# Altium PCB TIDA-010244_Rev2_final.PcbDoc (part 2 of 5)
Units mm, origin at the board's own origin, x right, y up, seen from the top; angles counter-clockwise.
Board outline 155.23 x 187.6 mm, 4 copper layers (GND/Signal 1, Solid GND Layer 1, Solid Power Layer 1, GND/Signal Layer 2), stack 1.59 mm thick; 350 components, 237 nets, 1153 pads, 380 vias.
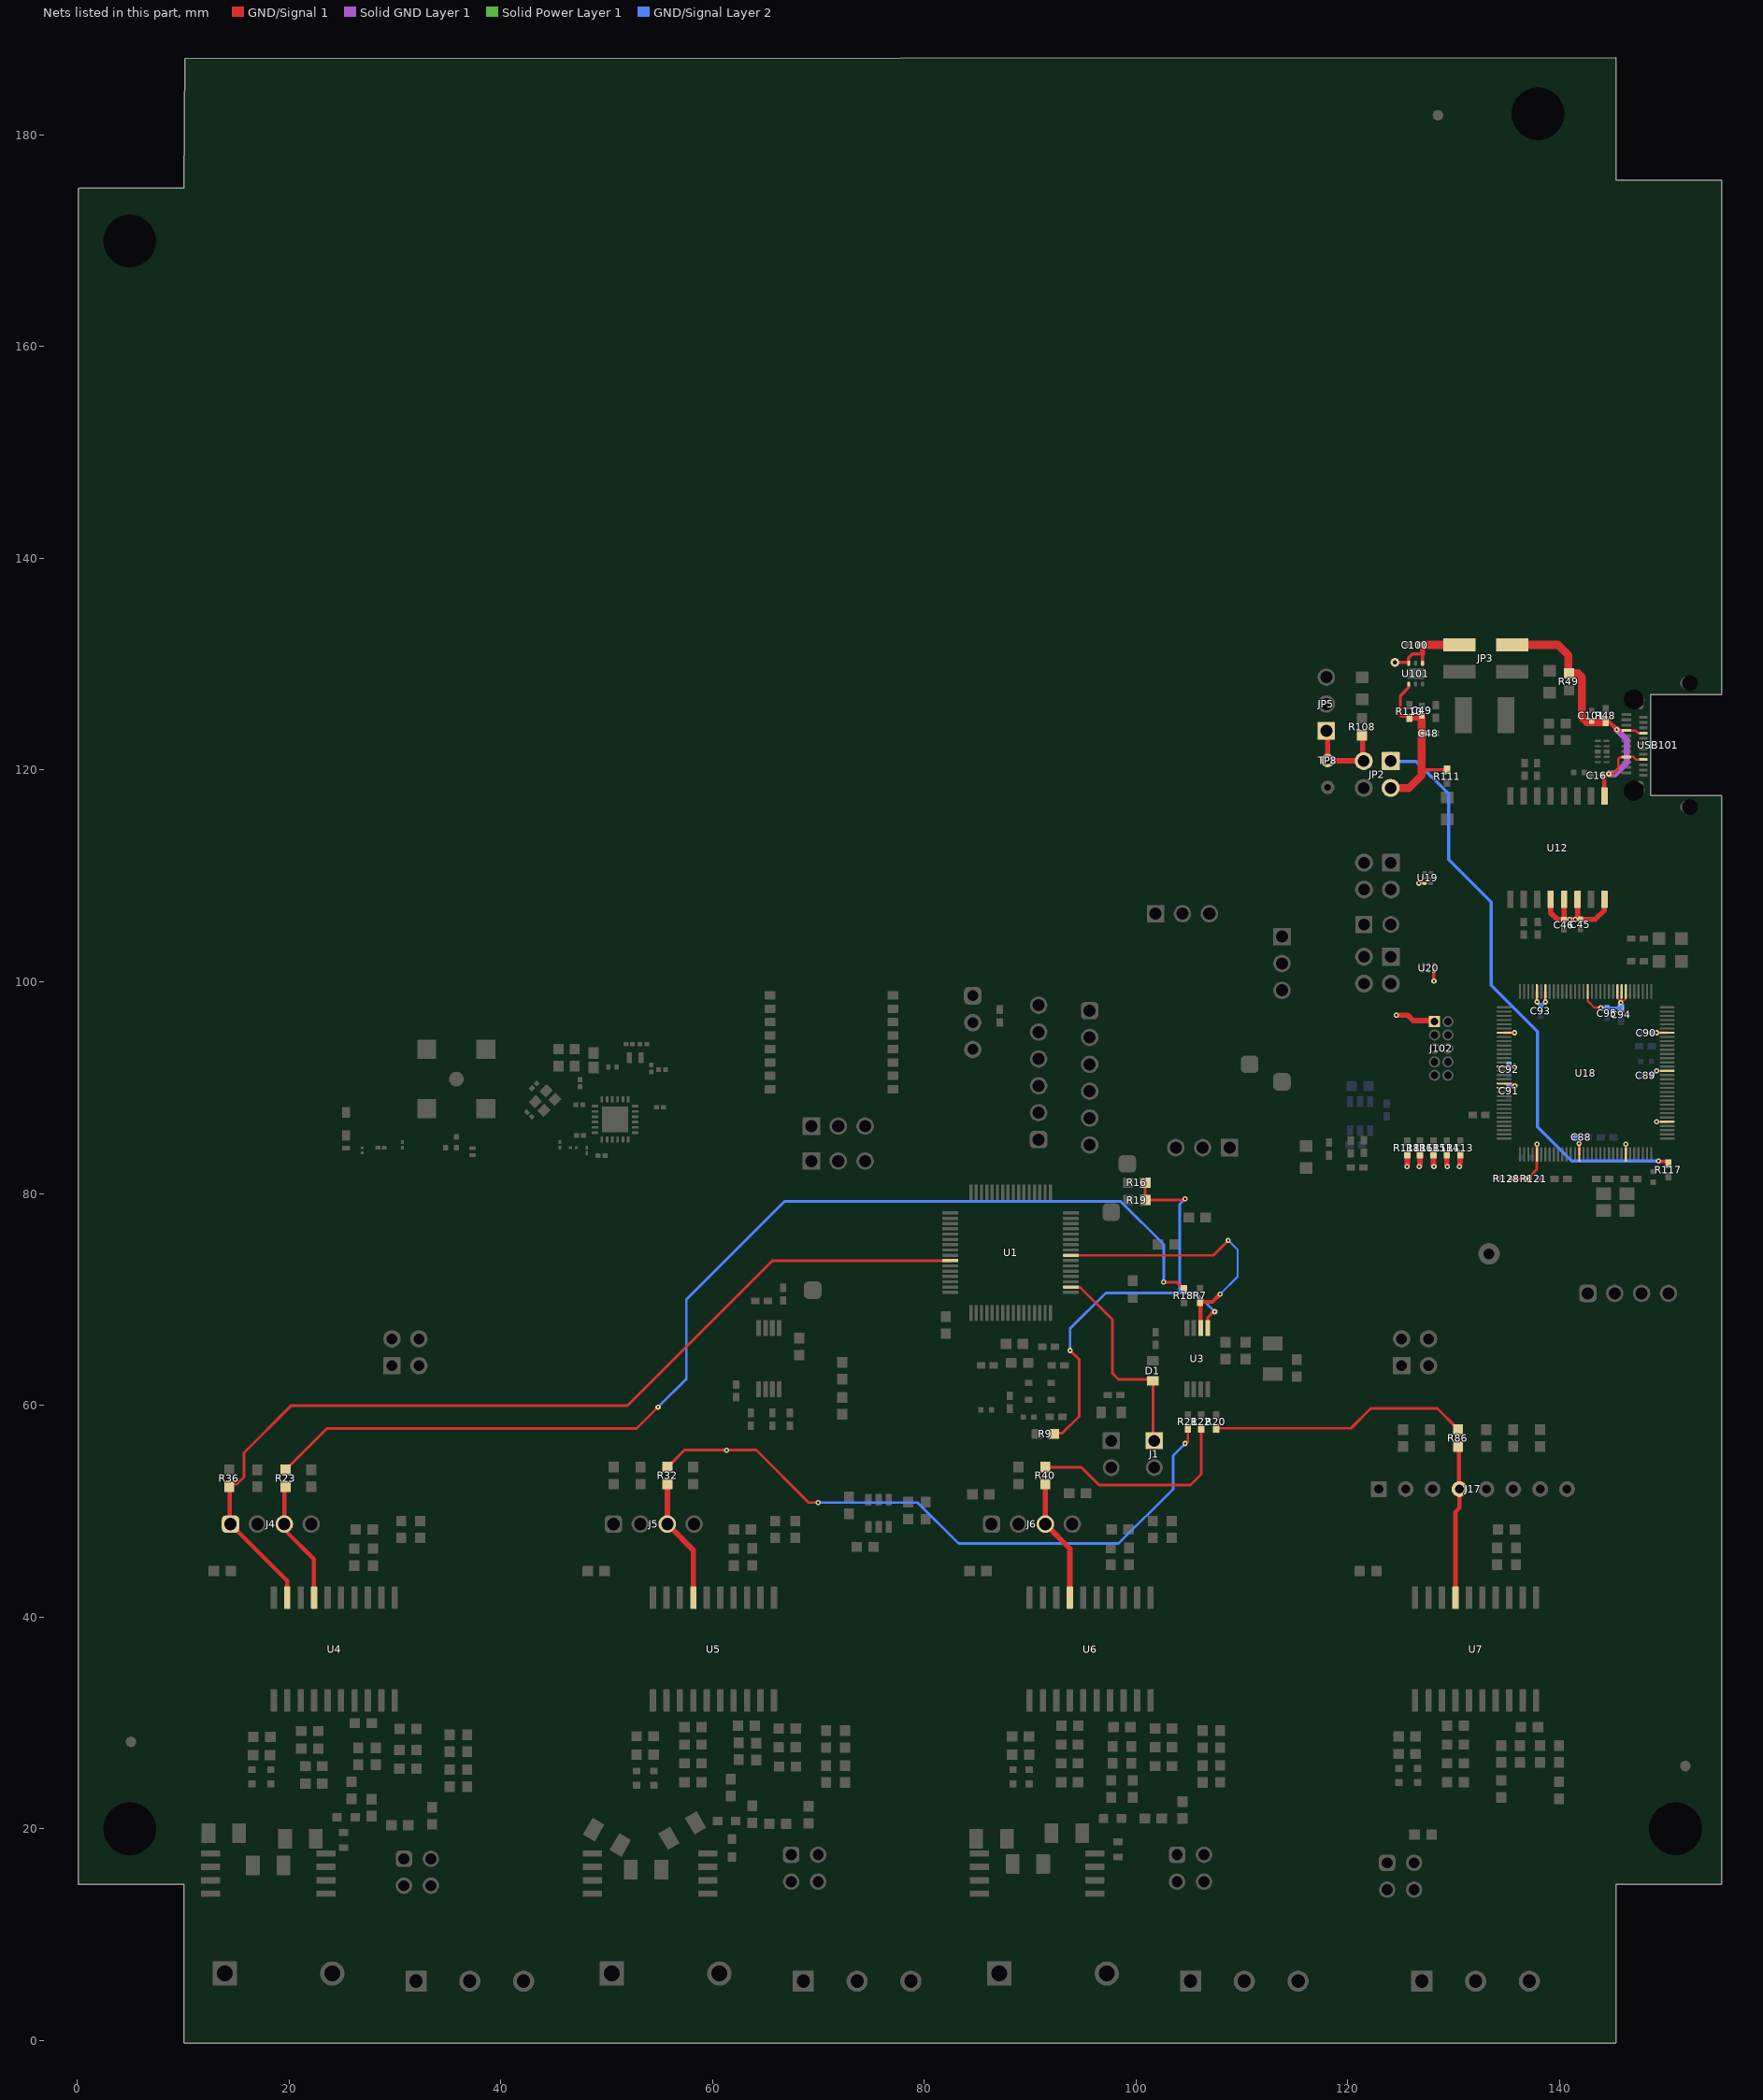
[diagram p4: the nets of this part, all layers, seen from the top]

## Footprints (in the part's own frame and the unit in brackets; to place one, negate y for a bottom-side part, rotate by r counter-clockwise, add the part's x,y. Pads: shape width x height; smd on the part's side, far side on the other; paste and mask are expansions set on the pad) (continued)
FP-MUP-U22001_CONN_USB_8MM94_8MM0-MFG [mm]
  rrect100% 0.6x1.9 hole 1.9 slot 0.6 at 0 deg: 1(-4.32,3.35) 2(4.32,3.35)
  round 1.207 smd: 1(-4.25,2.92) 2(4.25,2.92)
  round 1.207 smd far side: 1(-4.25,2.92) 2(4.25,2.92)
  rrect100% 1.25x0.7 hole 0.7 slot 1.25 at 0 deg: 1(-3.995,2.75) 2(3.995,2.75)
  rrect100% 0.7x1.5 hole 1.5 slot 0.7 at 0 deg: 3(-5.85,-1.95) 4(5.85,-1.95)
  round 1.17 smd far side: 3(-5.85,-1.625) 4(5.85,-1.625)
  round 1.17 smd: 3(-5.85,-1.625) 4(5.85,-1.625)
  rrect37% 0.27x0.9 smd: A1(-2.625,4.05) A2(-2.125,4.05) A3(-1.625,4.05) A4(-1.125,4.05) A5(-0.625,4.05) A6(-0.125,4.05) A7(0.375,4.05) A8(0.875,4.05) A9(1.375,4.05) A10(1.875,4.05) A11(2.375,4.05) A12(2.875,4.05)
  rrect37% 0.27x0.8 smd: B1(2.625,2.45) B2(2.125,2.45) B3(1.625,2.45) B4(1.125,2.45) B5(0.625,2.45) B6(0.125,2.45) B7(-0.375,2.45) B8(-0.875,2.45) B9(-1.375,2.45) B10(-1.875,2.45) B11(-2.375,2.45) B12(-2.875,2.45)
  GND/Signal 1 region: -6.5,-2.349 -6.5,-2.472 -6.411,-2.701 -6.244,-2.882 -6.023,-2.99 -5.9,-2.999 -5.9,-2.999 -5.833,-3.004 -5.699,-2.987 -5.572,-2.942 -5.457,-2.873 -5.358,-2.781 -5.281,-2.672 -5.227,-2.548 -5.2,-2.416 -5.2,-2.349 -5.2,-2.349 -5.2,-0.749 -5.2,-0.65 -5.276,-0.466 -5.417,-0.325 -5.601,-0.249 -5.7,-0.249 -5.7,-0.249 -6,-0.249 -6.099,-0.249 -6.283,-0.325 -6.424,-0.466 -6.5,-0.65 -6.5,-0.749 -6.5,-0.749
  GND/Signal 1 region: 6.5,-2.349 6.5,-2.472 6.411,-2.701 6.244,-2.882 6.023,-2.99 5.9,-2.999 5.833,-3.004 5.699,-2.987 5.572,-2.942 5.457,-2.873 5.358,-2.781 5.281,-2.672 5.227,-2.548 5.2,-2.416 5.2,-2.349 5.2,-2.349 5.2,-0.749 5.2,-0.65 5.276,-0.466 5.417,-0.325 5.601,-0.249 5.7,-0.249 5.7,-0.249 6,-0.249 6.099,-0.249 6.283,-0.325 6.424,-0.466 6.5,-0.65 6.5,-0.749 6.5,-0.749
  GND/Signal 1 region: -3.72,3.35 -3.72,4.05 -3.72,4.169 -3.811,4.39 -3.98,4.559 -4.201,4.65 -4.32,4.65 -4.439,4.65 -4.66,4.559 -4.829,4.39 -4.92,4.169 -4.92,4.05 -4.92,4.05 -4.92,2.85 -4.92,2.731 -4.829,2.51 -4.66,2.341 -4.439,2.25 -4.32,2.25 -4.32,2.25 -3.82,2.25 -3.711,2.25 -3.508,2.334 -3.354,2.488 -3.27,2.691 -3.27,2.8 -3.268,2.898 -3.332,3.082 -3.456,3.233 -3.624,3.332 -3.72,3.35
  GND/Signal 1 region: 3.72,3.35 3.72,4.05 3.72,4.169 3.811,4.39 3.98,4.559 4.201,4.65 4.32,4.65 4.439,4.65 4.66,4.559 4.829,4.39 4.92,4.169 4.92,4.05 4.92,4.05 4.92,2.85 4.92,2.731 4.829,2.51 4.66,2.341 4.439,2.25 4.32,2.25 4.32,2.25 3.82,2.25 3.711,2.25 3.508,2.334 3.354,2.488 3.27,2.691 3.27,2.8 3.268,2.898 3.332,3.082 3.456,3.233 3.624,3.332 3.72,3.35 3.72,3.35
  GND/Signal Layer 2 region: -6.5,-2.349 -6.5,-2.472 -6.411,-2.701 -6.244,-2.882 -6.023,-2.99 -5.9,-2.999 -5.833,-3.004 -5.699,-2.987 -5.572,-2.942 -5.457,-2.873 -5.358,-2.781 -5.281,-2.672 -5.227,-2.548 -5.2,-2.416 -5.2,-2.349 -5.2,-2.349 -5.2,-0.749 -5.2,-0.65 -5.276,-0.466 -5.417,-0.325 -5.601,-0.249 -5.7,-0.249 -5.7,-0.249 -6,-0.249 -6.099,-0.249 -6.283,-0.325 -6.424,-0.466 -6.5,-0.65 -6.5,-0.749 -6.5,-0.749
  GND/Signal Layer 2 region: 6.5,-2.349 6.5,-2.472 6.411,-2.701 6.244,-2.882 6.023,-2.99 5.9,-2.999 5.833,-3.004 5.699,-2.987 5.572,-2.942 5.457,-2.873 5.358,-2.781 5.281,-2.672 5.227,-2.548 5.2,-2.416 5.2,-2.349 5.2,-2.349 5.2,-0.749 5.2,-0.65 5.276,-0.466 5.417,-0.325 5.601,-0.249 5.7,-0.249 5.7,-0.249 6,-0.249 6.099,-0.249 6.283,-0.325 6.424,-0.466 6.5,-0.65 6.5,-0.749 6.5,-0.749
  GND/Signal Layer 2 region: -3.72,3.35 -3.72,4.05 -3.72,4.169 -3.811,4.39 -3.98,4.559 -4.201,4.65 -4.32,4.65 -4.439,4.65 -4.66,4.559 -4.829,4.39 -4.92,4.169 -4.92,4.05 -4.92,4.05 -4.92,2.85 -4.92,2.731 -4.829,2.51 -4.66,2.341 -4.439,2.25 -4.32,2.25 -4.32,2.25 -3.82,2.25 -3.711,2.25 -3.508,2.334 -3.354,2.488 -3.27,2.691 -3.27,2.8 -3.268,2.898 -3.332,3.082 -3.456,3.233 -3.624,3.332 -3.72,3.35
  GND/Signal Layer 2 region: 3.72,3.35 3.72,4.05 3.72,4.169 3.811,4.39 3.98,4.559 4.201,4.65 4.32,4.65 4.439,4.65 4.66,4.559 4.829,4.39 4.92,4.169 4.92,4.05 4.92,4.05 4.92,2.85 4.92,2.731 4.829,2.51 4.66,2.341 4.439,2.25 4.32,2.25 4.32,2.25 3.82,2.25 3.711,2.25 3.508,2.334 3.354,2.488 3.27,2.691 3.27,2.8 3.268,2.898 3.332,3.082 3.456,3.233 3.624,3.332 3.72,3.35
  Keep-Out Layer lines w0.2: -4.7,-3.5 -4.7,0.75 cw(c-4.7,1.25) -5.2,1.25 cw(c-4.7,1.25) -4.7,1.75 4.7,1.75 cw(c4.7,1.25) 5.2,1.25 cw(c4.7,1.25) 4.7,0.75 4.7,-3.5
  silkscreen extent -6,0.13 6,5.17, body extent -6.6,-4.23 6.6,4.75, height 0.25
FP-RT0603DRD07750RL_0603-MFG [mm]
  rrect13% 0.9x0.8 smd paste+0 mask+0: 1(-0.85,0) 2(0.85,0)
  silkscreen extent -0.85,-0.81 0.86,0.8, body extent -1.4,-0.55 1.4,0.55, height 0.25
FP-TZ3359DAAO73_SMT2_1MM65_1MM05-MFG [mm]
  rrect20% 0.5x1 smd paste+0 mask+0: 1(-0.55,0) 2(0.55,0)
  silkscreen extent -0.87,-0.87 0.87,0.87, body extent -0.97,-0.67 0.97,0.67, height 0.25
FP-TZ3908AAAO43_SMT4_2MM05_1MM65-MFG [mm]
  rrect12% 0.95x0.85 smd paste+0 mask+0: 1(-0.725,-0.575) 2(0.725,-0.575) 3(0.725,0.575) 4(-0.725,0.575)
  silkscreen extent -1.58,-1.67 1.58,0.88, body extent -1.3,-1.1 1.3,1.1, height 0.25
Hustsan_SMA-10V21-TGG [mm] "SMD, 4-Leads, Body 7.1x7.1mm"
  round 1.4 smd: 1(0,0)
  rect 1.8x1.8 smd: 2(-2.8,2.8) 3(-2.8,-2.8) 4(2.8,-2.8) 5(2.8,2.8)
  silkscreen extent -3.55,-3.55 3.55,3.55, body extent -3.55,-3.55 3.55,3.55, height 10.72
IEC_HighVoltage_Medium [mm]
  silkscreen extent -5.51,-4.46 5.51,5.09
Keystone5000 [mil] "For Keystone 500x miniature loop terminals"
  round 80 hole 40: 1(0,0)
  silkscreen extent -52,-52 52,52, body extent -49,-49 49,49, height 182
Label_650x200 [mil] "Thermal Transfer Label"
  round 1 on Mech13: 0(0,0)
  silkscreen extent -325,-100 325,100, body extent -325,-100 325,100, height 1
LTST-C170TBKT_Blue [mm] "LITE-ON"
  rect 1.2x1.2 smd: 1(-1.05,0) 2(1.05,0)
  silkscreen extent -1.6,-1 2.2,1, body extent -1.05,-0.67 1.05,0.67, height 1.2
Mill-Max_800-10-008-10-001000 [mm] "Mill-Max"
  rect 1.5x1.5 hole 0.85: 1(-8.89,0)
  round 1.5 hole 0.85: 2(-6.35,0) 3(-3.81,0) 4(-1.27,0) 5(1.27,0) 6(3.81,0) 7(6.35,0) 8(8.89,0)
  silkscreen extent -10.16,-1.27 10.16,1.78, body extent -10.16,-1.27 10.16,1.27, height 8.13
NDK_NX3225GA [mm] "NDK"
  rect 1.2x1.4 smd: 1(-0.8,1.1) 2(-0.8,-1.1) 3(0.8,-1.1) 4(0.8,1.1)
  silkscreen extent -1.9,-0.1 1.4,2, body extent -1.3,-1.65 1.3,1.65, height 0.9
On-Shore_ED120_3DS [mm] "ONSHORE"
  rrect5% 2x2 hole 1.25: 1(-5.08,0)
  round 2 hole 1.25: 2(0,0) 3(5.08,0)
  silkscreen extent -8.14,-4 7.5,5, body extent -8.32,-4 7.62,5, height 13
PDT0128A [mm] "Thin QFP, 128-Leads, Body 14x14mm, Pitch 0.4mm"
  oval 1.4x0.2 smd: 1(-7.7,6.2) 2(-7.7,5.8) 3(-7.7,5.4) 4(-7.7,5) 5(-7.7,4.6) 6(-7.7,4.2) 7(-7.7,3.8) 8(-7.7,3.4) 9(-7.7,3) 10(-7.7,2.6) 11(-7.7,2.2) 12(-7.7,1.8) 13(-7.7,1.4) 14(-7.7,1) 15(-7.7,0.6) 16(-7.7,0.2) 17(-7.7,-0.2) 18(-7.7,-0.6) 19(-7.7,-1) 20(-7.7,-1.4) 21(-7.7,-1.8) 22(-7.7,-2.2) 23(-7.7,-2.6) 24(-7.7,-3) 25(-7.7,-3.4) 26(-7.7,-3.8) 27(-7.7,-4.2) 28(-7.7,-4.6) 29(-7.7,-5) 30(-7.7,-5.4) 31(-7.7,-5.8) 32(-7.7,-6.2) 65(7.7,-6.2) 66(7.7,-5.8) 67(7.7,-5.4) 68(7.7,-5) 69(7.7,-4.6) 70(7.7,-4.2) 71(7.7,-3.8) 72(7.7,-3.4) 73(7.7,-3) 74(7.7,-2.6) 75(7.7,-2.2) 76(7.7,-1.8) 77(7.7,-1.4) 78(7.7,-1) 79(7.7,-0.6) 80(7.7,-0.2) 81(7.7,0.2) 82(7.7,0.6) 83(7.7,1) 84(7.7,1.4) 85(7.7,1.8) 86(7.7,2.2) 87(7.7,2.6) 88(7.7,3) 89(7.7,3.4) 90(7.7,3.8) 91(7.7,4.2) 92(7.7,4.6) 93(7.7,5) 94(7.7,5.4) 95(7.7,5.8) 96(7.7,6.2)
  oval 0.2x1.4 smd: 33(-6.2,-7.7) 34(-5.8,-7.7) 35(-5.4,-7.7) 36(-5,-7.7) 37(-4.6,-7.7) 38(-4.2,-7.7) 39(-3.8,-7.7) 40(-3.4,-7.7) 41(-3,-7.7) 42(-2.6,-7.7) 43(-2.2,-7.7) 44(-1.8,-7.7) 45(-1.4,-7.7) 46(-1,-7.7) 47(-0.6,-7.7) 48(-0.2,-7.7) 49(0.2,-7.7) 50(0.6,-7.7) 51(1,-7.7) 52(1.4,-7.7) 53(1.8,-7.7) 54(2.2,-7.7) 55(2.6,-7.7) 56(3,-7.7) 57(3.4,-7.7) 58(3.8,-7.7) 59(4.2,-7.7) 60(4.6,-7.7) 61(5,-7.7) 62(5.4,-7.7) 63(5.8,-7.7) 64(6.2,-7.7) 97(6.2,7.7) 98(5.8,7.7) 99(5.4,7.7) 100(5,7.7) 101(4.6,7.7) 102(4.2,7.7) 103(3.8,7.7) 104(3.4,7.7) 105(3,7.7) 106(2.6,7.7) 107(2.2,7.7) 108(1.8,7.7) 109(1.4,7.7) 110(1,7.7) 111(0.6,7.7) 112(0.2,7.7) 113(-0.2,7.7) 114(-0.6,7.7) 115(-1,7.7) 116(-1.4,7.7) 117(-1.8,7.7) 118(-2.2,7.7) 119(-2.6,7.7) 120(-3,7.7) 121(-3.4,7.7) 122(-3.8,7.7) 123(-4.2,7.7) 124(-4.6,7.7) 125(-5,7.7) 126(-5.4,7.7) 127(-5.8,7.7) 128(-6.2,7.7)
  silkscreen extent -7.7,-6.3 6.3,7, body extent -8,-8 8,8, height 1.07
PM0064A-MFG [mm]
  rrect33% 1.5x0.3 smd paste+0 mask+0: 1(-5.7,3.75) 2(-5.7,3.25) 3(-5.7,2.75) 4(-5.7,2.25) 5(-5.7,1.75) 6(-5.7,1.25) 7(-5.7,0.75) 8(-5.7,0.25) 9(-5.7,-0.25) 10(-5.7,-0.75) 11(-5.7,-1.25) 12(-5.7,-1.75) 13(-5.7,-2.25) 14(-5.7,-2.75) 15(-5.7,-3.25) 16(-5.7,-3.75) 33(5.7,-3.75) 34(5.7,-3.25) 35(5.7,-2.75) 36(5.7,-2.25) 37(5.7,-1.75) 38(5.7,-1.25) 39(5.7,-0.75) 40(5.7,-0.25) 41(5.7,0.25) 42(5.7,0.75) 43(5.7,1.25) 44(5.7,1.75) 45(5.7,2.25) 46(5.7,2.75) 47(5.7,3.25) 48(5.7,3.75)
  rrect33% 0.3x1.5 smd paste+0 mask+0: 17(-3.75,-5.7) 18(-3.25,-5.7) 19(-2.75,-5.7) 20(-2.25,-5.7) 21(-1.75,-5.7) 22(-1.25,-5.7) 23(-0.75,-5.7) 24(-0.25,-5.7) 25(0.25,-5.7) 26(0.75,-5.7) 27(1.25,-5.7) 28(1.75,-5.7) 29(2.25,-5.7) 30(2.75,-5.7) 31(3.25,-5.7) 32(3.75,-5.7) 49(3.75,5.7) 50(3.25,5.7) 51(2.75,5.7) 52(2.25,5.7) 53(1.75,5.7) 54(1.25,5.7) 55(0.75,5.7) 56(0.25,5.7) 57(-0.25,5.7) 58(-0.75,5.7) 59(-1.25,5.7) 60(-1.75,5.7) 61(-2.25,5.7) 62(-2.75,5.7) 63(-3.25,5.7) 64(-3.75,5.7)
  silkscreen extent -7.12,-5.1 5.1,5.1, body extent -6.55,-6.55 6.55,6.55, height 0.25
PW0008A-MFG [mm]
  rrect22% 1.5x0.45 smd paste+0 mask+0: 1(-2.9,0.975) 2(-2.9,0.325) 3(-2.9,-0.325) 4(-2.9,-0.975) 5(2.9,-0.975) 6(2.9,-0.325) 7(2.9,0.325) 8(2.9,0.975)
  silkscreen extent -4.37,-1.55 1.77,1.55, body extent -3.18,-1.68 3.22,1.32, height 1.2
RGE0024B-MFG [mm]
  rrect40% 0.6x0.25 smd paste+0 mask+0: 1(-1.9,1.25) 2(-1.9,0.75) 3(-1.9,0.25) 4(-1.9,-0.25) 5(-1.9,-0.75) 6(-1.9,-1.25) 13(1.9,-1.25) 14(1.9,-0.75) 15(1.9,-0.25) 16(1.9,0.25) 17(1.9,0.75) 18(1.9,1.25)
  rrect40% 0.25x0.6 smd paste+0 mask+0: 7(-1.25,-1.9) 8(-0.75,-1.9) 9(-0.25,-1.9) 10(0.25,-1.9) 11(0.75,-1.9) 12(1.25,-1.9) 19(1.25,1.9) 20(0.75,1.9) 21(0.25,1.9) 22(-0.25,1.9) 23(-0.75,1.9) 24(-1.25,1.9)
  rrect4% 2.45x2.45 smd paste-1000 mask+0: 25(0,0)
  silkscreen extent -2.87,-2.05 2.05,2.05, body extent -2.3,-2.3 2.3,2.3, height 0.25
Samtec_FTSH-105-01-x-D-K [mm] "Header, 1.27 mm, 5x2, TH"
  rect 1.05x1.05 hole 0.71: 1(-0.635,2.54)
  round 1.05 hole 0.71: 2(0.635,2.54) 3(-0.635,1.27) 4(0.635,1.27) 5(-0.635,0) 6(0.635,0) 7(-0.635,-1.27) 8(0.635,-1.27) 9(-0.635,-2.54) 10(0.635,-2.54)
  silkscreen extent -2.54,-3.17 2.54,3.2, body extent -2.54,-3.17 2.54,3.1, height 5.73
Samtec_SSW-102-01-x-D [mm] "Receptacle, 2.54mm, 2x2, TH"
  rrect50% 1.55x1.55 hole 1.04: 1(-1.27,1.27)
  round 1.55 hole 1.04: 2(-1.27,-1.27) 3(1.27,1.27) 4(1.27,-1.27)
  silkscreen extent -3.1,-2.48 2.79,2.48, body extent -2.79,-2.48 2.79,2.48, height 8.51
Samtec_TSM-102-01-x-DV [mm] "Header, 2.54mm, 2x2, SMT"
  rect 3.048x1.27 smd: 1(-2.475,-1.27) 2(2.475,-1.27) 3(-2.475,1.27) 4(2.475,1.27)
  silkscreen extent -1.75,-2.63 1.65,2.54, body extent -3.85,-2.54 3.85,2.54, height 9.65
TI_Stacked_Overlay_Small [mm]
  silkscreen extent -10.63,-2.49 10.63,2.49
TP_50MIL-25MILHOLE [mm]
  round 1.27 hole 0.635: 1(0,0)
TSW-102-07-G-D [mm] "Samtec 100mil, 2x2, 230 mil above insulator"
  rrect6% 1.65x1.65 hole 1.016: 1(-1.27,-1.27)
  round 1.65 hole 1.016: 2(-1.27,1.27) 3(1.27,-1.27) 4(1.27,1.27)
  silkscreen extent -3.56,-2.54 2.54,2.54, body extent -2.54,-2.54 2.54,2.54, height 8.38
TSW-103-07-G-S [mm] "Samtec 100mil, 1x3, 230 mil above insulator"
  rrect50% 1.65x1.65 hole 1.016: 1(-2.54,0)
  round 1.65 hole 1.016: 2(0,0) 3(2.54,0)
  body extent -3.81,-1.27 3.81,1.27, height 8.38
WEEE_Minimum [mm] "WEEElie bin"
  silkscreen extent -2.42,-4.38 2.52,2.65
WL-SICW_0805_L2W1.3H0.8 [mm] "SMT Infrared Chip LED Waterclear, body 2x1.3mm"
  rect 0.9x1.1 smd: 1(-0.95,0) 2(0.95,0)
  silkscreen extent -1,-1.05 -0.9,-0.95, body extent -1,-0.65 1,0.65, height 0.8
WL-SMCW_RED_0805 [mm] "SMD, 2-Leads, Body 1.6x0.8mm"
  rect 1.1x1.2 smd: 1(-1.05,0) 2(1.05,0)
  silkscreen extent -2.4,-1.1 1.5,1.1, body extent -1,-0.62 1,0.63, height 0.7
WURTH_61300311121 [mm] "Header, 2.54mm, 3x1, TH"
  rect 1.65x1.65 hole 1.15: 1(-2.54,0)
  round 1.65 hole 1.15: 2(0,0) 3(2.54,0)
  silkscreen extent -3.81,-1.27 3.81,1.6, body extent -3.81,-1.27 3.81,1.27, height 8.54
WURTH_61300411121 [mm] "Header, 2.54mm, 4x1, TH"
  rrect50% 1.65x1.65 hole 1.15: 1(-3.81,0)
  round 1.65 hole 1.15: 2(-1.27,0) 3(1.27,0) 4(3.81,0)
  body extent -5.08,-1.27 5.08,1.27, height 8.54
WURTH_61300611121 [mm] "Header, 2.54mm, 6x1, TH"
  rrect50% 1.65x1.65 hole 1.15: 1(-6.35,0)
  round 1.65 hole 1.15: 2(-3.81,0) 3(-1.27,0) 4(1.27,0) 5(3.81,0) 6(6.35,0)
  body extent -7.62,-1.27 7.62,1.27, height 8.54

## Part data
ANT1: library part CMP-0091830-1, "2.4-GHz Inverted F Antenna", Manufacturer="Texas Instruments", Operating Temperature Range=to
C1 C18 C25 C27 C33 C36 C38 C69 C79 C120: library part CMP-0006867-4, "CAP, CERM, 1 uF, 25 V, +/- 10%, X7R, 0603", Cap_Case=0603, Manufacturer=Kemet, Supplier Part Number 1=399-7376-1-ND, TempCo=X7R, Tolerance_%=10%, Value1=Unknown, Value2=25V, ValueDisplayed=1uF
C2: library part CMP-0007328-5, "CAP, CERM, 0.47 uF, 10 V, +/- 10%, X5R, 0603", Cap_Case=0603, Manufacturer=MuRata, Supplier Part Number 1=490-1539-1-ND, TempCo=X5R, Tolerance_%=10%, Value1=Unknown, Value2=10V, ValueDisplayed=0.47uF
C3 C15: library part CMP-0086193-1, "CAP, CERM, 10 µF, 10 V,+/- 10%, X5R, 0603", Cap_Case=0603, Manufacturer=MuRata, TempCo=X5R, Tolerance_%=10%, Value2=10V, ValueDisplayed=10µF
C4 C102: library part CMP-0001348-1, "Chip Multilayer Ceramic Capacitors for General Purpose, 0201, 15pF, C0G, 30ppm/°C, 2%, 50V", Manufacturer=Murata, Operating Temperature Range="-55°C to +125°C", TempCo=30ppm/°C, Temperature Characteristic=C0G, Tolerance_%=2%, ValueDisplayed=15pF
C5: library part CMP-0090363-1, "10000pF ±10% 25V Ceramic Capacitor X7R 0402 (1005 Metric)", Digikey Part Number=732-7545-1-ND, Manufacturer="Wurth Electronics", Mouser Part Number=710-885012205050, Operating Temperature Range="-55°C to +125°C", TempCo=15%, Temperature Characteristic=X7R, Tolerance_%=10%, ValueDisplayed=10nF
C6: library part CMP-0006629-2, "CAP, CERM, 0.1 uF, 10 V, +/- 10%, X7R, 0402", Cap_Case=0402, Manufacturer=MuRata, Supplier Part Number 1=GRM155R71A104KA01D-ND, TempCo=X7R, Tolerance_%=10%, Value1=Unknown, Value2=10V, ValueDisplayed=0.1uF
C7 C8: library part CMP-0006658-2, "CAP, CERM, 0.01 uF, 25 V, +/- 10%, X7R, 0402", Cap_Case=0402, Manufacturer=MuRata, Supplier Part Number 1=490-1312-1-ND, TempCo=X7R, Tolerance_%=10%, Value1=Unknown, Value2=25V, ValueDisplayed=0.01uF
C9: library part CMP-0079607-1, "CAP, CERM, 1 µF, 16 V,+/- 10%, X7R, AEC-Q200 Grade 1, 0603", Cap_Case=0603, Manufacturer=TDK, Supplier Part Number 1=445-12539-1-ND, TempCo=X7R, Tolerance_%=10%, Value2=16V, ValueDisplayed=1µF
C10 C12: library part CMP-0006420-2, "CAP, CERM, 15 pF, 50 V, +/- 5%, C0G/NP0, 0402", Cap_Case=0402, Manufacturer=MuRata, Supplier Part Number 1=81-GRM1555C1H150JA1D, TempCo=C0G/NP0, Tolerance_%=5%, Value1=Unknown, Value2=50V, ValueDisplayed=15pF
C11: library part CMP-0090362-1, "0.1µF ±10% 10V Ceramic Capacitor X7R 0402 (1005 Metric)", Digikey Part Number=732-7513-1-ND, Manufacturer="Wurth Electronics", Mouser Part Number=710-885012205018, Operating Temperature Range="-55°C to +125°C", TempCo=15%, Temperature Characteristic=X7R, Tolerance_%=10%, ValueDisplayed=0.1uF
C13 C14 C17 C20 C23 C24 C29 C32 C35 C40 C43 C68 C71 C74: library part CMP-0007044-5, "CAP, CERM, 0.1 uF, 50 V, +/- 10%, X7R, 0603", Cap_Case=0603, Manufacturer=TDK, Supplier Part Number 1=445-1314-1-ND, TempCo=X7R, Tolerance_%=10%, Value1="0.0296 ohm", Value2=50V, ValueDisplayed=0.1uF
C16 C44 C45 C46 C92 C93 C98 C99: library part CMP-0090362-1, "0.1µF ±10% 10V Ceramic Capacitor X7R 0402 (1005 Metric)", Digikey Part Number=732-7513-1-ND, Manufacturer="Wurth Electronics", Mouser Part Number=710-885012205018, Operating Temperature Range="-55°C to +125°C", TempCo=15%, Temperature Characteristic=X7R, Tolerance_%=10%, ValueDisplayed=100000pF
C19 C21 C22 C26 C28 C30 C31 C34 C37 C39 C41 C42 C70 C72 C73 C121: library part CMP-0006847-4, "CAP, CERM, 1000 pF, 50 V, +/- 10%, X7R, 0603", Cap_Case=0603, Manufacturer=Kemet, Supplier Part Number 1=399-1082-1-ND, TempCo=X7R, Tolerance_%=10%, Value1=Unknown, Value2=50V, ValueDisplayed=1000pF
C47: library part CMP-0009297-2, "CAP, CERM, 0.01 uF, 1500 V, +/- 10%, X7R, 1812", Cap_Case=1812, Manufacturer=AVX, Supplier Part Number 1=478-4735-1-ND, TempCo=X7R, Tolerance_%=10%, Value1="0.05 ohm", Value2=1500V, ValueDisplayed=0.01uF
C48 C88 C94 C96 C97 C100: library part CMP-0064924-2, "CAP, CERM, 1 uF, 10 V,+/- 20%, X5R, 0402", Cap_Case=0402, Manufacturer="Wurth Elektronik", Supplier Part Number 1=732-7489-1-ND, TempCo=X5R, Tolerance_%=20%, Value1=Unknown, Value2=10V, ValueDisplayed=1uF
C49 C87 C89 C90 C91 C95: library part CMP-0090363-1, "10000pF ±10% 25V Ceramic Capacitor X7R 0402 (1005 Metric)", Digikey Part Number=732-7545-1-ND, Manufacturer="Wurth Electronics", Mouser Part Number=710-885012205050, Operating Temperature Range="-55°C to +125°C", TempCo=15%, Temperature Characteristic=X7R, Tolerance_%=10%, ValueDisplayed=10000pF
C50 C52 C53 C55 C56 C58 C59 C61 C62 C64 C65 C67 C75 C77: library part CMP-0006822-4, "CAP, CERM, 100 pF, 50 V, +/- 5%, C0G/NP0, 0603", Cap_Case=0603, Manufacturer="Wurth Elektronik", TempCo=C0G/NP0, Tolerance_%=5%, Value1=Unknown, Value2=50V, ValueDisplayed=100pF
C51 C54 C57 C60 C63 C66 C76: library part CMP-0006941-4, "CAP, CERM, 4700 pF, 100 V, +/- 5%, C0G/NP0, 0603", Cap_Case=0603, Manufacturer=Kemet, Supplier Part Number 1=399-9974-1-ND, TempCo=C0G/NP0, Tolerance_%=5%, Value1=Unknown, Value2=100V, ValueDisplayed=4700pF
C78 C80: library part CMP-0006979-5, "CAP, CERM, 0.1 uF, 25 V, +/- 10%, X7R, 0603", Cap_Case=0603, Manufacturer=Kemet, Supplier Part Number 1=399-5345-1-ND, TempCo=X7R, Tolerance_%=10%, Value1=Unknown, Value2=25V, ValueDisplayed=0.1uF
C81 C103: library part CMP-0009664-3, "CAP, CERM, 12 pF, 50 V, +/- 5%, C0G/NP0, 0201", Cap_Case=0201, Manufacturer=MuRata, Supplier Part Number 1=490-6114-1-ND, TempCo=C0G/NP0, Tolerance_%=5%, Value1=Unknown, Value2=50V, ValueDisplayed=12pF
C101: library part CMP-0092424-1, "Cap Cer 3300pF 50V X7R 0402", Digikey Part Number=732-7559-1-ND, Manufacturer="Wurth Electronics", Mouser Part Number=710-885012205064, Operating Temperature Range="-55°C to +125°C", TempCo=15%, Temperature Characteristic=X7R, Tolerance_%=10%, ValueDisplayed=3.3nF
C104: library part CMP-0092999-1, "Chip Multilayer Ceramic Capacitors for General Purpose, 0402, 1.0uF, X7R, 15%, 10%, 10V", Manufacturer=Murata, Operating Temperature Range="-55°C to +125°C", TempCo=15%, Temperature Characteristic=X7R, Tolerance_%=10%, ValueDisplayed=1.0uF
C105 C106 C107 C110 C111 C116: library part CMP-0064969-1, "CAP, CERM, 0.1 uF, 10 V,+/- 10%, X7S, 0201", Cap_Case=0201, Manufacturer=MuRata, Supplier Part Number 1=490-14450-1-ND, TempCo=X7S, Tolerance_%=10%, Value1=Unknown, Value2=10V, ValueDisplayed=0.1uF
C108 C112: library part CMP-0087107-2, "Chip Multilayer Ceramic Capacitors for General Purpose", Manufacturer=Murata, TempCo=15%, Tolerance_%=10%
C113 C117: library part CMP-0090358-1, "15pF ±5% 50V Ceramic Capacitor C0G, NP0 0402 (1005 Metric)", Digikey Part Number=732-7470-1-ND, Manufacturer="Wurth Electronics", Mouser Part Number=710-885012005056, Operating Temperature Range="-55°C to +125°C", TempCo=30ppm/°C, Temperature Characteristic=NP0, Tolerance_%=5%, ValueDisplayed=15pF
C114 C115: library part CMP-06035-002174-1, "Chip Multilayer Ceramic Capacitors for General Purpose, 0201, 1.5pF, C0G, 30ppm/°C, 0.1pF, 50V", Case Code (Imperial)=0201, Case Code (Metric)=0603, Dielectric=C0G, Max Operating Temperature=125°C, Min Operating Temperature=-55°C, Package Quantity=50000, Voltage Rating=50V
C118: library part CMP-2010-01514-2, "Chip Multilayer Ceramic Capacitors for General Purpose, 0201, 1.2pF, C0G, 30ppm/°C, 0.1pF, 50V", Case Code (Imperial)=0201, Case Code (Metric)=0603, Dielectric=C0G, Max Operating Temperature=125°C, Min Operating Temperature=-55°C, Package Quantity=50000, Voltage Rating=50V
C119: library part CMP-06035-002085-1, "Chip Multilayer Ceramic Capacitors for General Purpose, 0201, 0.70pF, C0G, 30ppm/°C, 0.1pF, 50V", Case/Package=0201, Dielectric=C0G, Max Operating Temperature=125°C, Min Operating Temperature=-55°C, Voltage Rating=50V
C122 C123: library part CMP-0006415-2, "CAP, CERM, 12 pF, 50 V, +/- 5%, C0G/NP0, 0402", Cap_Case=0402, Manufacturer=MuRata, Supplier Part Number 1=14T3292, TempCo=C0G/NP0, Tolerance_%=5%, Value1=Unknown, Value2=50V, ValueDisplayed=12pF
D1 D2: library part CMP-03913-108242144-1, "15408094BA400 Ir Emitter, 940Nm, 0805 Rohs Compliant: Yes", Forward Current=1A, Forward Voltage=1.2V, Max Operating Temperature=85°C, Max Reverse Voltage (DC)=5V, Min Operating Temperature=-40°C
D6: library part CMP-0073606-3, "1-Channel ESD Protection Diode for USB Type-C and Antenna Protection, DPY0002A (X1SON-2)", Alternate Manufacturer="Texas Instruments", Alternate PartNumber=TPD1E0B04DPYT, Operating Temperature Range="-40 to 125 C", Rating=Catalog
FB1 FB2 FB3 FB4 FB5 FB6 FB7 FB8: library part CMP-0092964-1, "Chip Ferrite Bead, 0603, 1000Ω @ 100MHz, 0.5Ω, 25%, 450mA", Impedance At Frequency="1000Ω @ 100MHz", Manufacturer=Murata, Operating Temperature Range="-55°C to +125℃", Test Frequency=100MHz, Tolerance_%=25%
FID1 FID2 FID3: library part CMP-0077181-1, "Fiducial mark.  There is nothing to buy or mount.", Manufacturer=N/A
H1 H2 H3 H4: library part CMP-0079337-1, "5 mm PCB Hole", Manufacturer=Any
J1 J3: library part CMP-0075197-1, "Header, 2.54mm, 2x1, TH", Color=Black, Current_A=2A, Manufacturer=3M, Supplier Part Number 1=3M9447-ND, Voltage_V=1kV
J2: library part CMP-0075197-1, "Header, 2.54mm, 2x1, TH", Color=Black, Current_A=2A, Manufacturer=3M, PartNumber=961102-6404-AR, Supplier Part Number 1=3M9447-ND, Voltage_V=1kV
J4 J5 J6 J26: library part CMP-0054798-2, "Header, 2.54 mm, 4x1, Gold, TH", Color=Black, Manufacturer="Wurth Elektronik", PartNumber=61300411121, Supplier Part Number 1=732-5317-ND
J7 J8: library part CMP-0054801-2, "Header, 2.54 mm, 6x1, Gold, TH", Color=Black, Manufacturer="Wurth Elektronik", Supplier Part Number 1=732-5319-ND
J9 J18 JP2: library part CMP-0092422-1, "THT Vertical Pin Header WR-PHD, Pitch 2.54 mm, Dual Row, 4 pins", Current_A=3A, Digikey Part Number=732-5294-ND, Manufacturer="Wurth Electronics", Mouser Part Number=710-61300421121, Operating Temperature Range="-40°C to +105°C", Voltage_V=250V
J10 J11 J12: library part CMP-0109233-1, "2 Position Wire to Board Terminal Block Horizontal with Board 0.400\" (10.16mm) Through Hole", Current_A=14A, Digikey Part Number=732-11177-ND, Manufacturer="Wurth Electronics", Mouser Part Number=710-691216610002, Operating Temperature Range="-30°C to +120°C", Voltage_V=300V
J13 J14 J15 J16: library part CMP-0074911-1, "Terminal Block, 5.08 mm, 3x1, Brass, TH", Color=Blue, Current_A=15A, Manufacturer="On-Shore Technology", Supplier Part Number 1=ED1610-ND, Voltage_V=300V
J17: library part CMP-0055090-1, "Header, 100mil, 8x1, TH", Manufacturer=Mill-Max, Supplier Part Number 1=ED7208-ND
J19 J20 J22 J23: library part CMP-0055713-1, "Receptacle, 2.54mm, 2x2, Gold, TH", Color=Black, Current_A=4.7A, Manufacturer=Samtec, Supplier Part Number 1=SAM1208-02-ND, Voltage_V=465V
J21: library part CMP-0055832-1, "Connector, SMA, Vertical, Gold, SMT", Manufacturer="Hus-Tsan Group Co., Ltd."
J24 J25: library part CMP-0075404-1, "Header, 100mil, 2x2, Gold, TH", Color=Black, Current_A=6.3A, Manufacturer=Samtec, Supplier Part Number 1=SAM1028-02-ND, Voltage_V=550V
J102: library part CMP-0075533-1, "Header, 1.27 mm, 5x2, Gold, TH", Color=Black, Manufacturer=Samtec, Supplier Part Number 1=FTSH-105-01-F-D-K-ND
JP1: library part CMP-0075407-2, "Header, 100mil, 3x1, Gold, TH", Color=Black, Current_A=6.3A, Manufacturer=Samtec, Supplier Part Number 1=SAM1029-03-ND, Voltage_V=550V
JP3: library part CMP-0055559-1, "Header, 2.54mm, 2x2, Gold, SMT", Color=Black, Manufacturer=Samtec, Supplier Part Number 1=TSM-102-01-L-DV-ND, Voltage_V=475V
JP4 JP5 JP6 JP7 JP8 JP9: library part CMP-0054796-1, "Header, 2.54 mm, 3x1, Gold, TH", Manufacturer="Wurth Elektronik", Supplier Part Number 1=732-5316-ND
L1: library part CMP-0003124-1, "Ferrite Bead, 600 ohm @ 100 MHz, 0.5 A, 1206", Manufacturer="Wurth Elektronik", Supplier Part Number 1=732-4655-1-ND, Value1="0.3 ohm", Value2=0.5A, ValueDisplayed="600 ohm"
L3: library part CMP-06042-017052-1, "Multilayer type Inductor for Power Lines 10uH ±20% @1MHz, 300mA, Max DCR 1.365Ω, SRF 32MHz"
L4: library part CMP-0001349-1, "Film type RF Inductor 2.8nH ±0.1nH 500mA 0.2Ω 0201 (0603)", Manufacturer=Murata, Operating Temperature Range="-55°C to +125°C", Self Resonant Frequency=9.5GHz, Test Frequency=500MHz, Tolerance_%=0.1nH
L5: library part CMP-06042-009700-1, "Film type RF Inductor 2nH ±0.1nH 600mA 0.15Ω 0201 (0603)"
LBL1: library part CMP-0003625-1, "Thermal Transfer Printable Labels, 0.650\" W x 0.200\" H - 10,000 per roll", Manufacturer=Brady, Supplier Part Number 1=97C5133
LED0 LED1 LED6 LED7: library part CMP-0002951-3, "LED, Red, SMD", Color=Red, Manufacturer="Wurth Elektronik", Power_TotalModule=72mW, Value1=0.072W, Value2=1.9V
LED2 LED3: library part CMP-0002889-2, "LED, Blue, SMD", Color=Blue, Manufacturer=Lite-On, Value1=W, Value2=3.3V
Logo1: library part CMP-0074838-1, "Texas Instrument Corporate Signature"
Logo2: library part CMP-0074844-1
Logo3: library part CMP-0074847-1, "FCC_disclaimer"
Logo4: library part CMP-0074769-1
LOGO5 LOGO6 LOGO7 LOGO8: library part CMP-0074835-1, "IEC 61010-1 High Voltage Warning"
MD1: library part CMP-0123405-1, "Bluetooth 5.3 Module Hardware", Manufacturer="Shenzhen Shengrun Technology", Max Frequency=2.4835GHz, Max Supply Voltage=3.8V, Min Supply Voltage=2.2V, Operating Temperature Range="-40°C to +125°C", Receiving Current=5.3mA, Transmitting Current=12mA
R1 R2 R119 R120: library part CMP-0026736-1, "RES, 470, 1%, 0.063 W, 0402", Manufacturer="Yageo America", Power_W=63mW, Supplier Part Number 1=311-470LRCT-ND, TempCo="100 ppm/C", Tolerance_%=1%, Value2=0.063W, Value_Code=470R, ValueDisplayed=470
R3 R10: library part CMP-0026935-3, "RES, 47 k, 5%, 0.063 W, AEC-Q200 Grade 0, 0402", Manufacturer=Vishay-Dale, Power_W=63mW, Supplier Part Number 1=541-47KJCT-ND, TempCo="200 ppm/C", Tolerance_%=5%, Value2=0.063W, Value_Code=47k0, ValueDisplayed=47k
R4: library part CMP-0026890-5, "RES, 2.2 k, 5%, 0.063 W, AEC-Q200 Grade 0, 0402", Manufacturer=Vishay-Dale, Power_W=63mW, Supplier Part Number 1=541-2.2KJCT-ND, TempCo="200 ppm/C", Tolerance_%=5%, Value2=0.063W, Value_Code=2k20, ValueDisplayed=2.2k
R5: library part CMP-0026822-3, "RES, 0, 5%, 0.063 W, AEC-Q200 Grade 0, 0402", Manufacturer=Vishay-Dale, Power_W=63mW, Supplier Part Number 1=541-0.0JCT-ND, TempCo="200 ppm/C", Tolerance_%=5%, Value2=0.063W, Value_Code=0000, ValueDisplayed=0
R6: library part CMP-0025769-4, "RES, 2.2 k, 5%, 0.1 W, AEC-Q200 Grade 0, 0603", Manufacturer=Vishay-Dale, Power_W=100mW, Supplier Part Number 1=541-2.2KGCT-ND, TempCo="200 ppm/C", Tolerance_%=5%, Value2=0.1W, Value_Code=2k20, ValueDisplayed=2.2k
R7 R47 R121 R124: library part CMP-0026825-5, "RES, 10 k, 5%, 0.063 W, AEC-Q200 Grade 0, 0402", Manufacturer=Vishay-Dale, Power_W=63mW, Supplier Part Number 1=541-10KJCT-ND, TempCo="200 ppm/C", Tolerance_%=5%, Value2=0.063W, Value_Code=10k0, ValueDisplayed=10k
R8 R50 R51 R52 R53: library part CMP-0027004-2, "RES, 0, 5%, 0.063 W, 0402", Manufacturer="Yageo America", Power_W=63mW, Supplier Part Number 1=311-0.0JRCT-ND, TempCo="200 ppm/C", Tolerance_%=5%, Value2=0.063W, Value_Code=0000, ValueDisplayed=0
R9 R16 R19 R23 R28 R32 R35 R40 R44 R86 R89: library part CMP-0025874-4, "RES, 0, 5%, 0.1 W, AEC-Q200 Grade 0, 0603", Manufacturer=Panasonic, Power_W=100mW, Supplier Part Number 1=P0.0GCT-ND, TempCo="600 ppm/C", Tolerance_%=5%, Value2=0.1W, Value_Code=0000, ValueDisplayed=0
R11: library part CMP-0094948-1, "0 Ohms Jumper 0.1W, 1/10W Chip Resistor 0402 (1005 Metric) - Thick Film", Digikey Part Number=2679-CR0402-10W-000TTR-ND, Manufacturer=Venkel, Operating Temperature Range="-55°C to +155°C", Power_W=100mW
R12 R13 R15 R17 R18 R20 R21 R22: library part CMP-0026908-1, "RES, 33, 5%, 0.063 W, 0402", Manufacturer=Vishay-Dale, Power_W=63mW, Supplier Part Number 1=541-33JCT-ND, TempCo="200 ppm/C", Tolerance_%=5%, Value2=0.063W, Value_Code=33R0, ValueDisplayed=33
R14: library part CMP-0026908-2, "RES, 33, 5%, 0.063 W, 0402", Manufacturer=Vishay-Dale, Power_W=63mW, Supplier Part Number 1=541-33JCT-ND, TempCo="200 ppm/C", Tolerance_%=5%, Value2=0.063W, Value_Code=33R0, ValueDisplayed=33
R24 R25 R31 R36 R39 R42 R99: library part CMP-0021990-4, "RES, 100 k, 1%, 0.1 W, AEC-Q200 Grade 0, 0603", Manufacturer=Vishay-Dale, Power_W=100mW, Supplier Part Number 1=541-100KHCT-ND, TempCo="100 ppm/C", Tolerance_%=1%, Value2=0.1W, Value_Code=100k
R26 R27 R29 R30 R33 R34 R37 R38 R41 R43 R45 R46 R87 R88 R90 R91: library part CMP-0025787-4, "RES, 33, 5%, 0.1 W, AEC-Q200 Grade 0, 0603", Manufacturer=Vishay-Dale, Power_W=100mW, Supplier Part Number 1=541-33GCT-ND, TempCo="200 ppm/C", Tolerance_%=5%, Value2=0.1W, Value_Code=33R0, ValueDisplayed=33
R48: library part CMP-0026100-2, "RES, 1.00 M, 1%, 0.063 W, AEC-Q200 Grade 0, 0402", Manufacturer=Vishay-Dale, Power_W=63mW, Supplier Part Number 1=541-1.00MLCT-ND, TempCo="100 ppm/C", Tolerance_%=1%, Value2=0.063W, Value_Code=1M00, ValueDisplayed=1.00M
R49 R108: library part CMP-0025921-5, "RES, 3.0 k, 5%, 0.1 W, 0603", Manufacturer=Yageo, Power_W=100mW, Supplier Part Number 1=311-3.0KGRCT-ND, TempCo="100 ppm/C", Tolerance_%=5%, Value2=0.1W, Value_Code=3k00, ValueDisplayed=3.0k
R54 R55: library part CMP-0025932-5, "RES, 5.1 k, 5%, 0.1 W, 0603", Manufacturer=Yageo, Power_W=100mW, Supplier Part Number 1=311-5.1KGRCT-ND, TempCo="100 ppm/C", Tolerance_%=5%, Value2=0.1W, Value_Code=5k10, ValueDisplayed=5.1k
R56 R61 R62 R67 R68 R73: library part CMP-0022448-2, "RES, 49.9, 1%, 0.1 W, 0603", Manufacturer=Vishay-Dale, Power_W=100mW, Supplier Part Number 1=541-49.9HCT-ND, TempCo="100 ppm/C", Tolerance_%=1%, Value2=0.1W, Value_Code=49R9, ValueDisplayed=49.9
R57 R63 R69 R125: library part CMP-0088453-2, "750 Ohms ±0.5% 0.1W, 1/10W Chip Resistor 0603 (1608 Metric)  Thin Film", Digikey Part Number=311-750DCT-ND, Manufacturer=Yageo, Mouser Part Number=603-RT0603DRD07750RL, Operating Temperature Range="-55°C to +155°C", Power_W=100mW, TempCo=25ppm/°C, Tolerance_%=0.5%
R58 R59 R60 R64 R65 R66 R70 R71 R72: library part CMP-0018656-3, "RES, 330 k, 5%, 0.25 W, AEC-Q200 Grade 0, 1206", Manufacturer=Vishay-Dale, Power_W=250mW, Supplier Part Number 1=541-330KECT-ND, TempCo="200 ppm/C", Tolerance_%=5%, Value2=0.25W, Value_Code=330k
R74 R76 R78 R80 R82 R84 R92 R94 R100 R101 R102 R103 R104 R105 R106: library part CMP-0025885-5, "RES, 0, 5%, 0.1 W, 0603", Manufacturer=Yageo, Power_W=100mW, Supplier Part Number 1=311-0.0GRCT-ND, TempCo="200 ppm/C", Tolerance_%=5%, Value2=0.1W, Value_Code=0000, ValueDisplayed=0
R75 R77 R79 R81 R83 R85 R93 R95: library part CMP-0022448-4, "RES, 49.9, 1%, 0.1 W, AEC-Q200 Grade 0, 0603", Manufacturer=Vishay-Dale, Power_W=100mW, Supplier Part Number 1=541-49.9HCT-ND, TempCo="100 ppm/C", Tolerance_%=1%, Value2=0.1W, Value_Code=49R9, ValueDisplayed=49.9
R96 R97 R98: library part CMP-0025080-3, "RES, 2.00 k, 0.5%, 0.1 W, 0603", Manufacturer="Yageo America", Power_W=100mW, TempCo="25 ppm/C", Tolerance_%=0.5%, Value2=0.1W, Value_Code=2k00, ValueDisplayed=2.00k
R109 R111: library part CMP-0026962-3, "RES, 680, 5%, 0.063 W, AEC-Q200 Grade 0, 0402", Manufacturer=Vishay-Dale, Power_W=63mW, Supplier Part Number 1=541-680JCT-ND, TempCo="200 ppm/C", Tolerance_%=5%, Value2=0.063W, Value_Code=680R, ValueDisplayed=680
R110: library part CMP-0026441-2, "RES, 52.3 k, 1%, 0.063 W, AEC-Q200 Grade 0, 0402", Manufacturer=Vishay-Dale, Power_W=63mW, Supplier Part Number 1=541-52.3KLCT-ND, TempCo="100 ppm/C", Tolerance_%=1%, Value2=0.063W, Value_Code=52k3, ValueDisplayed=52.3k
R112: library part CMP-0078244-2, "RES, 30.0 k, 1%, 0.063 W, AEC-Q200 Grade 0, 0402", Manufacturer=Vishay-Dale, Power_W=63mW, Supplier Part Number 1=541-30.0KLCT-ND, TempCo="100 ppm/C", Tolerance_%=1%, Value2=0.063W, Value_Code=30k0, ValueDisplayed=30.0k
R113 R114 R115 R116: library part CMP-0026071-3, "RES, 1.00 k, 1%, 0.063 W, AEC-Q200 Grade 0, 0402", Manufacturer=Vishay-Dale, Power_W=63mW, Supplier Part Number 1=541-1.00KLCT-ND, TempCo="100 ppm/C", Tolerance_%=1%, Value2=0.063W, Value_Code=1k00, ValueDisplayed=1.00k
R117: library part CMP-0026824-3, "RES, 100, 5%, 0.063 W, AEC-Q200 Grade 0, 0402", Manufacturer=Vishay-Dale, Power_W=63mW, Supplier Part Number 1=541-100JCT-ND, TempCo="200 ppm/C", Tolerance_%=5%, Value2=0.063W, Value_Code=100R, ValueDisplayed=100
R118: library part CMP-0026918-5, "RES, 3.3 k, 5%, 0.063 W, AEC-Q200 Grade 0, 0402", Manufacturer=Vishay-Dale, Power_W=63mW, Supplier Part Number 1=541-3.3KJCT-ND, TempCo="200 ppm/C", Tolerance_%=5%, Value2=0.063W, Value_Code=3k30, ValueDisplayed=3.3k
R122: library part CMP-0027943-1, "RES, 100 k, 1%, 0.05 W, 0201", Manufacturer="Yageo America", Power_W=50mW, Supplier Part Number 1=603-RC0201FR-7D100KL, TempCo="200 ppm/C", Tolerance_%=1%, Value2=0.05W, Value_Code=100k
R123 R127: library part CMP-0097819-1, "0 Ohms ±1% Chip Resistor 0603 (1608 Metric) Thick Film", Digikey Part Number=2997-CR160000FTR-ND, Manufacturer="Meritek Electronics", Max Current=2A, Operating Temperature Range="-55°C to +155°C", Power_W=100mW, Tolerance_%=1%
R126: library part CMP-0026413-2, "RES, 4.87 k, 1%, 0.063 W, AEC-Q200 Grade 0, 0402", Manufacturer=Vishay-Dale, Power_W=63mW, Supplier Part Number 1=541-4.87KLCT-ND, TempCo="100 ppm/C", Tolerance_%=1%, Value2=0.063W, Value_Code=4k87, ValueDisplayed=4.87k
R128: library part CMP-0026946-3, "RES, 51, 5%, 0.063 W, AEC-Q200 Grade 0, 0402", Manufacturer=Vishay-Dale, Power_W=63mW, Supplier Part Number 1=541-51JCT-ND, TempCo="200 ppm/C", Tolerance_%=5%, Value2=0.063W, Value_Code=51R0, ValueDisplayed=51
TP1: library part CMP-0055137-1, "Test Point, Miniature, Red, TH", Color=Red, Manufacturer=Keystone, Supplier Part Number 1=36-5000-ND
TP4 TP8: library part CMP-0078143-3, "TEST POINT.  No entry in BOM.", Manufacturer=N/A
U1: library part CMP-0093960-1, "Mixed-Signal Microcontrollers With CAN-FD Interface LQFP64", Frequency_Fixed=80MHz, Manufacturer="Texas Instruments", Max Supply Voltage=3.6V, Min Supply Voltage=1.62V, Operating Temperature Range="-40°C to +125°C"
U2 U3: library part CMP-0096980-1, "1.8-V, 2.5-V, and 3.3-V LVCMOS Clock Buffer Family", Digikey Part Number=296-LMK1C1104PWRCT-ND, Manufacturer="Texas Instruments", Max Supply Voltage=3.465V, Min Supply Voltage=1.71V, Mouser Part Number=595-LMK1C1104PWR, Nominal Supply Current=25-33000uA, Operating Temperature Range="-40°C to +125°C"
U4 U5 U6 U7: library part CMP-0093943-1, "3-Channel, Simultaneously-Sampling, 24-Bit, Reinforced Isolated DeltaSigma ADC With Integrated DC/DC Converter", Manufacturer="Texas Instruments", Max Supply Voltage=5.5V, Min Supply Voltage=3V, Operating Temperature Range="-40°C to +125°C"
U8: library part CMP-0092928-2, "3-Axis Linear Hall Effect Sensor With I2C Interface SOT23-6", Manufacturer="Texas Instruments", Max Supply Voltage=3.6V, Min Supply Voltage=1.7V, Operating Supply Current=2.3-2.7mA, Operating Temperature Range="-40°C to +125°C"
U10: library part CMP-0067340-2, "High-Accuracy, Fixed-Threshold OV/UV Monitor, DDC0006A (SOT-23-T-6)", Alternate Manufacturer="Texas Instruments", Alternate PartNumber=TPS3702CX33DDCT
U12: library part CMP-0091303-1, "Full/Low Speed Isolated USB Repeater, SOIC16-Wide", Manufacturer="Texas Instruments", Max Supply Voltage=5.5V, Min Supply Voltage=3V, Nominal Supply Current=9-9.5mA, Operating Temperature Range="-55°C to +150°C"
U13: library part CMP-0073613-3, "4-Channel Ultra-Low-Capacitance IEC ESD Protection Diode, DQA0010A (USON-10)", Alternate Manufacturer="Texas Instruments"
U14: library part CMP-0033813-1, "SimpleLink™ Bluetooth ® 5.3 Low Energy Wireless MCU QFN24 48MHz Arm® Cortex®-M0+ 28KB RAM 256KB FLASH", Frequency_Fixed=48MHz, Manufacturer="Texas Instruments", Max Supply Voltage=3.8V, Min Supply Voltage=1.71V, Operating Temperature Range="-40°C to +125°C"
U15 U16 U17: library part CMP-0121043-1, Manufacturer="Texas Instruments", Operating Temperature Range=to
U18: library part CMP-0077953-1, "MSP432E401YTPDT, PDT0128A (TQFP-128)", Alternate Manufacturer="Texas Instruments", Alternate PartNumber=MSP432E401YTPDTR
U19 U20: library part CMP-0043115-3, "4-Channel ESD Protection Array for High-Speed Data Interfaces, DRY0006A (USON-6)", Breakdown Voltage(Min)(V)=6, IO Capacitance(Typ)(pF)=1.6, IO Leakage Current(nA)=1, Manufacturer="Texas Instruments", Operating Temperature Range="-40 to 85 C", Rating=Catalog
U101: library part CMP-0066914-5, "1% High-Accuracy, 1-A, Low-Dropout Regulator with Reverse Current Protection, DRV0006A (WSON-6)", Alternate Manufacturer="Texas Instruments", Alternate PartNumber=TPS7A3701DRVT
USB101: library part CMP-0092137-1, "Connector, USB Type-C 24 pin Mid Mount dual row Receptacle Surface Mount", Manufacturer=MUP, Operating Temperature Range="-25°C to +85°C"
Y1: library part CMP-0094615-2, "Crystal replacement: Ultra-low Power LVCMOS Oscillator 4-pin, VSON 3.2 x 2.5 x 0.9mm", Frequency Stability=20ppm, Frequency_Fixed=50MHz, Load Capacitance=15pF, Manufacturer="Texas Instruments", Max Supply Current=4mA, Max Supply Voltage=3.465V, Min Supply Voltage=2.375V, Operating Temperature Range="to +135°C"
Y2: library part CMP-0004635-3, "Crystal, 16 MHz, 8pF, SMD", Frequency Stability=+/-30ppm, Frequency_Fixed=16MHz, Manufacturer=NDK, Supplier Part Number 1=644-1157-1-ND
Y3: library part CMP-0001358-1, "Crystal Unit 1.6x1.0 Tuning Fork 32.768KHz", Frequency Stability=380ppm, Frequency Tolerance=20ppm, Frequency_Fixed=32.768kHz, Load Capacitance=7pF, Manufacturer="TAI-SAW Technology", Operating Temperature Range="-40°C to +125°C"
Y4: library part CMP-0001392-1, "Crystal Unit SMD 2.0x1.6 48.0MHz", Frequency Stability=30ppm, Frequency Tolerance=5ppm, Frequency_Fixed=48MHz, Load Capacitance=7pF, Manufacturer="TAI-SAW Thechnology", Operating Temperature Range="-40°C to +125°C"
ZZ1: library part CMP-0003616-3
ZZ2: library part CMP-0077236-1
ZZ3: library part CMP-0077237-1
ZZ4: library part CMP-0077238-1

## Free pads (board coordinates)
  rrect50% 1.65x1.65 smd: 3(69.469,70.866) 3(97.663,78.232) 3(113.792,90.551) 4(99.187,82.804) 4(110.744,92.202)

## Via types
v1: diameter 0.5, hole 0.2, GND/Signal 1 to GND/Signal Layer 2, tented both sides, 236 vias
v2: diameter 0.5, hole 0.2, GND/Signal 1 to GND/Signal Layer 2, 46 vias
v3: diameter 0.864, hole 0.406, GND/Signal 1 to GND/Signal Layer 2, 41 vias
v4: diameter 0.7, hole 0.4, GND/Signal 1 to GND/Signal Layer 2, tented both sides, 40 vias
v5: diameter 0.61, hole 0.203, GND/Signal 1 to GND/Signal Layer 2, tented both sides, 10 vias
v6: diameter 0.4, hole 0.2, GND/Signal 1 to GND/Signal Layer 2, tented both sides, 7 vias

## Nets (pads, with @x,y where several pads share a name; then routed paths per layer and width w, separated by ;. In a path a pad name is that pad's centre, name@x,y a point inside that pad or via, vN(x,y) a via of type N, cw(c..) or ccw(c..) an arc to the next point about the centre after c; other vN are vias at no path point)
+3V3_XDS110: C45.2 C46.2 C48.1 C49.2 C88.1 C89.2 C90.2 C91.2 C92.2 C93.2 C94.1 C95.2 J102.1 JP2.3 R110.2 R111.2 R113.2 R114.2 R115.2 R116.2 R118.2 R121.2 R128.2 U12.12 U12.13 U12.14 U12.16 U18.7 U18.8 U18.9 U18.16 U18.26 U18.28 U18.39 U18.47 U18.51 U18.52 U18.69 U18.79 U18.90 U18.101 U18.113 U18.122 U19.6 U20.6 U101.1 | length 68.8
  GND/Signal 1 w0.15: v1@149.098,91.567 149.115,91.584 v1(149.187,91.584) U18.113@150.169,91.584
  GND/Signal 1 w0.16: U18.9@145.469,99.084 145.469,98.473 145.529,98.413 145.529,98.403 v1@145.779,98.154 ; v1@145.796,98.171 145.831,98.171 145.861,98.201 145.861,99.077 U18.8@145.869,99.084 ; v1@145.974,98.109 146.209,98.343 146.209,98.413 146.269,98.473 U18.7@146.269,99.084
  GND/Signal 1 w0.2: U18.52@134.769,89.984 135.7,89.984 135.886,90.17 v1@135.89,90.17 ; U18.51@134.769,90.384 135.534,90.384 v1@135.748,90.17 ; U18.47@134.769,91.984 135.727,91.984 v1@135.763,91.948 ; U18.16@142.669,99.084 142.669,98.184 143.302,97.551 v1(143.908,97.551) ; v1@149.225,86.741 149.268,86.784 U18.101@150.169,86.784
  GND/Signal 1 w0.254: U18.39@134.769,95.184 v1(135.751,95.184) ; R128.2@135.591,81.39 136.96,81.39 R121.2@136.969,81.381 ; R121.2@137.037,81.313 R121.2@136.969,81.381 ; v1(137.869,84.666) U18.69@137.869,83.684 137.869,82.281 R121.2@136.969,81.381 ; v1(137.869,98.102) U18.28@137.869,99.084 ; v1(138.669,98.102) U18.26@138.669,99.084 ; U18.79@141.862,83.678 v1@141.862,84.701 ; U18.90@146.269,83.684 v1(146.269,84.666) ; v1(149.187,95.184) U18.122@150.169,95.184
  GND/Signal 1 w0.3: U101.1@125.759,128.133 125.759,127.791 124.968,127 124.968,125.222 125.095,125.095 R110.2@125.984,125.095 ; v1(126.708,109.314) 127.252,109.314 U19.6@127.264,109.302 ; 127.108,120.021 R111.2@129.388,120.021 ; v1(128.14,100.077) U20.6@128.14,101.018
  GND/Signal 1 w0.5: v1(124.585,96.848) 125.677,96.848 126.187,96.338 J102.1@128.201,96.338 ; U12.12@139.167,107.788 139.167,106.515 139.779,105.903 C46.2@140.437,105.903 ; C46.2@140.421,105.884 140.437,105.9 C46.2@140.437,105.903 ; U12.13@140.437,107.788 C46.2@140.437,105.903 ; v1@141.707,105.988 U12.14@141.707,107.788 ; U12.16@144.247,107.788 144.247,106.763 143.387,105.903 C46.2@140.437,105.903
  GND/Signal 1 w0.508: v1(125.603,82.55) 125.623,82.57 R118.2@125.623,83.691 ; R110.2@125.878,124.952 C49.2@126.803,124.952 ; v1(126.746,82.55) 126.827,82.631 R116.2@126.827,83.695 ; R115.2@128.097,83.695 128.097,82.596 v1(128.143,82.55) ; R114.2@129.367,83.695 129.367,82.596 v1(129.413,82.55) ; v1(130.556,82.55) 130.591,82.585 130.591,83.649 R113.2@130.637,83.695 130.637,83.03
  GND/Signal 1 w0.762: JP2.3@124.054,118.313 125.798,118.313 126.991,119.506 126.991,124.841
  Solid Power Layer 1 w0.762: JP2.3@123.693,118.313 JP2.3@124.054,118.313
  GND/Signal Layer 2 w0.254: C92.2@135.237,92.21 135.463,91.984 v1(135.751,91.984) ; v1(137.869,98.102) 138.23,97.741 C93.2@138.23,97.72 138.287,97.72 v1(138.669,98.102) ; C88.1@141.466,85.313 141.869,84.91 141.846,84.887 v1(141.846,84.73) ; v1(143.908,97.551) 143.908,97.533 143.893,97.518 C94.1@145.765,97.518 ; v1(145.796,98.044) 145.801,98.039 C94.1@145.801,97.481 ; C89.2@148.684,91.135 149.133,91.584 v1(149.187,91.584) ; C90.2@148.707,95.179 148.712,95.184 v1(149.187,95.184)
  GND/Signal Layer 2 w0.3: C91.2@135.237,90.231 135.278,90.19 v1(135.78,90.19)
  other v1: 149.187,86.784 140.97,105.893 141.503,105.9
+5V0_MCU: JP2.2 JP5.1 R108.2 TP8.1 | length 11.9
  GND/Signal 1 w0.5: TP8.1@118.11,120.904 JP5.1@118.11,123.698 ; TP8.1@118.135,120.879 JP2.2@121.488,120.879 ; R108.2@121.406,123.298 121.406,120.961 JP2.2@121.488,120.879 ; JP2.2@121.514,120.853 JP2.2@121.488,120.879
  GND/Signal Layer 2 w0.5: TP8.1@118.237,120.904 118.262,120.879 121.488,120.879 JP2.2@121.514,120.853
+5V0_USB: C16.2 C101.2 JP3.1 R48.2 R49.2 U12.1 USB101.A4 USB101.A9 USB101.B4 USB101.B9 | length 31.6
  GND/Signal 1 w0.22: v1(144.653,119.634) 144.707,119.688 145.162,119.688 145.542,120.068 145.542,121.001 145.76,121.219 146.294,121.219 USB101.A4@146.319,121.244 146.98,121.244 147.23,120.994 USB101.B9@147.919,120.994 ; v1@145.572,123.744 USB101.A9@146.319,123.744 147.177,123.744 147.402,123.519 147.894,123.519 USB101.B4@147.919,123.494
  GND/Signal 1 w0.381: C16.2@144.069,119.529 144.069,119.566 144.553,119.566 144.621,119.634 v1(144.653,119.634) ; U12.1@144.247,117.538 C16.2@144.247,119.405
  GND/Signal 1 w0.4: R48.2@144.145,124.714 144.526,124.714 v1(145.415,123.825)
  GND/Signal 1 w0.762: JP3.1@135.52,131.825 139.868,131.825 140.852,130.841 R49.2@140.852,129.222 ; R49.2@140.903,129.141 141.751,129.141 142.129,128.763 142.129,124.991 142.584,124.536 R48.2@144.145,124.536
  Solid GND Layer 1 w0.6: v1(144.653,119.634) 145.288,119.634 146.356,120.702 146.356,122.884 v1(145.415,123.825)
+5V0_XDS110: C100.1 JP2.1 JP3.2 R117.1 U101.4 U101.6 | length 64.2
  GND/Signal 1 w0.3: v3(124.46,130.175) 125.667,130.175 125.684,130.158 125.759,130.158 U101.6@125.759,130.083 ; U101.6@125.73,130.158 125.73,130.592 126.111,130.973 127.059,130.973 U101.4@127.059,130.116 ; v1(149.352,83.058) 149.39,83.02 150.14,83.02 150.29,82.87 R117.1@150.29,82.827
  GND/Signal 1 w0.5: C100.1@126.975,131.807 127.059,131.723 127.059,130.973
  GND/Signal 1 w0.762: C100.1@127.031,131.825 JP3.2@130.57,131.825
  Solid Power Layer 1 w0.8: JP2.1@124.054,121.303 JP2.1@124.079,121.278
  GND/Signal Layer 2 w0.3: JP2.1@124.308,120.824 126.47,120.824 129.543,117.751 129.543,111.54 133.563,107.52 133.563,99.66 137.909,95.314 137.909,86.299 141.15,83.058 v1(149.352,83.058) ; JP2.1@124.444,120.315 JP2.1@124.444,120.61
ACT: D1.1 J1.1 U1.50 | length 20
  GND/Signal 1 w0.254: U1.50@93.866,71.157 93.889,71.134 94.735,71.134 97.79,68.079 97.79,62.992 98.361,62.42 D1.1@101.6,62.42 ; D1.1@101.6,62.296 101.6,56.769 J1.1@101.727,56.642
ADC_CLK: R9.2 R16.2 R19.2 U3.1 | length 43.9
  GND/Signal 1 w0.254: R9.2@92.116,57.341 93.019,57.341 94.634,58.956 94.634,64.307 v1(93.777,65.164) ; R19.2@100.876,79.375 104.454,79.375 104.581,79.502 v1(104.648,79.502) ; R16.2@100.876,81.026 100.876,79.591 R19.2@100.965,79.502 ; U3.1@106.766,67.289 106.766,68.285 v1@107.379,68.897
  GND/Signal Layer 2 w0.254: v1(93.777,65.164) 93.777,67.234 97.155,70.612 104.14,70.612 105.655,70.612 v1@107.433,68.834 ; 104.14,70.637 104.14,78.994 v1(104.648,79.502)
  other v1: 107.442,68.834
ADC_CLK_EN: R7.1 U1.56 U3.2 | length 26.3
  GND/Signal 1 w0.254: U1.56@93.866,74.157 107.304,74.157 v1(108.712,75.565)
  GND/Signal 1 w0.381: R7.1@106.045,69.758 107.223,69.758 v1(107.95,70.485) ; R7.1@106.081,69.758 106.081,67.323 U3.2@106.116,67.289
  GND/Signal Layer 2 w0.2: v1(107.95,70.485) 109.601,72.136 109.601,74.676 v1(108.712,75.565)
ADC_CLKIN_1: R18.2 R23.2 | length 105.5
  GND/Signal 1 w0.254: R23.2@19.685,53.886 19.685,53.911 20.033,54.259 20.058,54.259 23.584,57.785 52.832,57.785 v1(54.864,59.817) ; v1(102.616,71.628) 103.851,71.628 104.248,71.231 104.348,71.231 104.521,71.058 R18.2@104.521,70.958 ; R18.2@104.59,71.104 R18.2@104.682,71.012
  GND/Signal Layer 2 w0.254: v1(54.864,59.817) 57.531,62.484 57.531,69.977 66.802,79.248 98.552,79.248 102.616,75.184 v1(102.616,71.628)
ADC_CLKIN_1_H: J4.3 R23.1 U4.17 | length 12.3
  GND/Signal 1 w0.381: J4.3@19.558,48.768 19.558,51.976 19.652,52.07 R23.1@19.685,52.07 ; J4.3@19.801,48.757 19.801,48.182 19.812,48.171 19.812,48.006 22.352,45.466 U4.17@22.352,40.894
ADC_CLKIN_2: R21.2 R32.2 | length 60.5
  GND/Signal 1 w0.254: R32.2@55.753,54.14 55.753,54.165 56.101,54.513 56.126,54.513 57.366,55.753 v1@61.214,55.753 ; v1(61.341,55.753) 64.135,55.753 69.088,50.8 v1(69.977,50.8) ; v1(104.648,56.388) 104.775,56.515 104.902,56.515 R21.2@104.902,57.82
  GND/Signal Layer 2 w0.254: v1(69.977,50.8) 79.375,50.8 83.248,46.926 98.361,46.926 103.505,52.07 103.505,55.245 v1(104.648,56.388)
ADC_CLKIN_2_H: J5.3 R32.1 U5.17 | length 11.4
  GND/Signal 1 w0.508: J5.3@55.728,48.768 55.74,48.781 55.74,52.565 R32.1@55.753,52.578 ; J5.3@55.982,48.514 58.191,46.304 U5.17@58.191,41.807
ADC_CLKIN_3: R22.2 R40.2 | length 20.2
  GND/Signal 1 w0.254: R40.2@91.44,54.14 94.831,54.14 96.52,52.451 105.156,52.451 106.172,53.467 R22.2@106.172,57.82
ADC_CLKIN_3_H: J6.3 R40.1 U6.17 | length 11.5
  GND/Signal 1 w0.508: R40.1@91.313,52.451 91.44,52.324 J6.3@91.44,48.768 ; J6.3@91.567,48.641 93.751,46.457 U6.17@93.751,41.807
ADC_CLKIN_4: R20.2 R86.2 | length 24.5
  GND/Signal 1 w0.254: R20.2@107.569,57.82 120.304,57.82 122.174,59.69 128.46,59.69 130.238,57.912 R86.2@130.556,57.912
ADC_CLKIN_4_H: J17.4 R86.1 U7.17 | length 14.5
  GND/Signal 1 w0.406: U7.17@130.175,41.807 130.175,49.911 130.556,50.292 J17.4@130.556,52.07 130.493,52.133 130.493,55.816 R86.1@130.683,56.007
ADC_CS1: J4.1 R36.1 U1.26 U4.19 | length 90.9
  GND/Signal 1 w0.254: R36.1@14.351,52.286 14.588,52.523 15.058,52.523 15.748,53.213 15.748,55.499 20.193,59.944 51.943,59.944 65.656,73.657 U1.26@82.466,73.657
  GND/Signal 1 w0.381: R36.1@14.414,52.197 14.414,48.831 J4.1@14.478,48.768 19.832,43.414 U4.19@19.832,41.812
